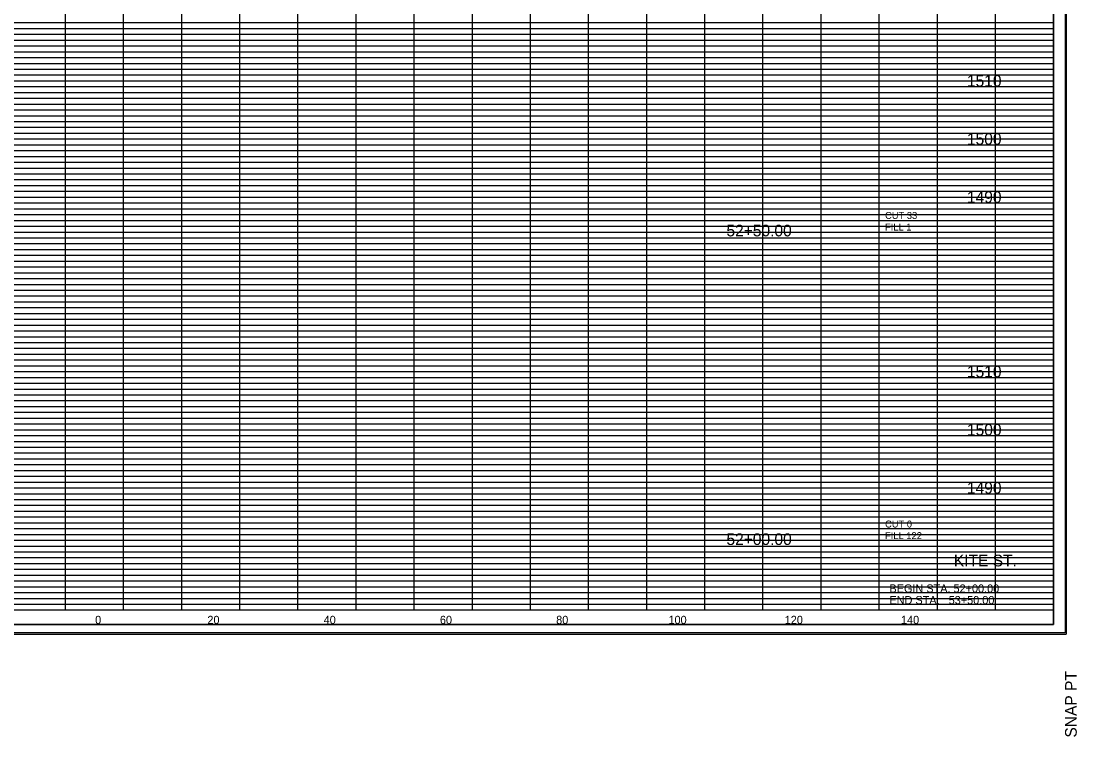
# Model space of a CAD drawing. Extents: x 980 to 1324, y 978 to 1497.
# Drawn here: x 1142.4 to 1324, y 1248.2 to 1371.3 of the extents above; entities that cross this region are included whole.
import ezdxf

# ---------------------------------------------------------------- set-up
doc = ezdxf.new("R2010")
doc.units = 0
for name, color, linetype in [('DESIGN - SHEET - Corner Text', 7, 'Continuous'), ('DESIGN - SHEET - Light Grid', 7, 'Continuous'), ('DESIGN - SHEET - Linework', 7, 'Continuous'), ('DESIGN - SHEET - Plot Shape', 7, 'Continuous'), ('DESIGN - TYPICAL - Text', 7, 'Continuous')]:
    doc.layers.add(name, color=color, linetype=linetype)

# ---------------------------------------------------------------- blocks, each defined once
blk = doc.blocks.new('XSTSHT')
at = {"layer": 'DESIGN - SHEET - Light Grid'}
for p, q in [((8, 10.1), (16, 10.1)), ((16, 10.1), (24, 10.1)), ((24, 10.1), (32, 10.1)), ((8, 9.9), (16, 9.9)), ((16, 9.9), (24, 9.9)), ((24, 9.9), (32, 9.9)), ((8, 9.8), (16, 9.8)), ((8, 9.7), (16, 9.7)), ((16, 9.8), (24, 9.8)), ((16, 9.7), (24, 9.7)), ((24, 9.8), (32, 9.8)), ((24, 9.7), (32, 9.7)), ((8, 9.6), (16, 9.6)), ((8, 9.5), (16, 9.5)), ((16, 9.6), (24, 9.6)), ((16, 9.5), (24, 9.5)), ((24, 9.6), (32, 9.6)), ((24, 9.5), (32, 9.5)), ((8, 9.4), (16, 9.4)), ((8, 9.3), (16, 9.3)), ((16, 9.4), (24, 9.4)), ((16, 9.3), (24, 9.3)), ((24, 9.4), (32, 9.4)), ((24, 9.3), (32, 9.3)), ((8, 9.2), (16, 9.2)), ((8, 9.1), (16, 9.1)), ((16, 9.2), (24, 9.2)), ((16, 9.1), (24, 9.1)), ((24, 9.2), (32, 9.2)), ((24, 9.1), (32, 9.1)), ((8, 8.9), (16, 8.9)), ((16, 8.9), (24, 8.9)), ((24, 8.9), (32, 8.9)), ((8, 8.8), (16, 8.8)), ((16, 8.8), (24, 8.8)), ((24, 8.8), (32, 8.8)), ((8, 8.7), (16, 8.7)), ((8, 8.6), (16, 8.6)), ((16, 8.7), (24, 8.7)), ((16, 8.6), (24, 8.6)), ((24, 8.7), (32, 8.7)), ((24, 8.6), (32, 8.6)), ((8, 8.5), (16, 8.5)), ((8, 8.4), (16, 8.4)), ((16, 8.5), (24, 8.5)), ((16, 8.4), (24, 8.4)), ((24, 8.5), (32, 8.5)), ((24, 8.4), (32, 8.4)), ((8, 8.3), (16, 8.3)), ((8, 8.2), (16, 8.2)), ((16, 8.3), (24, 8.3)), ((16, 8.2), (24, 8.2)), ((24, 8.3), (32, 8.3)), ((24, 8.2), (32, 8.2)), ((8, 8.1), (16, 8.1)), ((16, 8.1), (24, 8.1)), ((24, 8.1), (32, 8.1)), ((8, 7.9), (16, 7.9)), ((16, 7.9), (24, 7.9)), ((24, 7.9), (32, 7.9)), ((8, 7.8), (16, 7.8)), ((8, 7.7), (16, 7.7)), ((16, 7.8), (24, 7.8)), ((16, 7.7), (24, 7.7)), ((24, 7.8), (32, 7.8)), ((24, 7.7), (32, 7.7)), ((8, 7.6), (16, 7.6)), ((8, 7.5), (16, 7.5)), ((16, 7.6), (24, 7.6)), ((16, 7.5), (24, 7.5)), ((24, 7.6), (32, 7.6)), ((24, 7.5), (32, 7.5)), ((8, 7.4), (16, 7.4)), ((8, 7.3), (16, 7.3)), ((16, 7.4), (24, 7.4)), ((16, 7.3), (24, 7.3)), ((24, 7.4), (32, 7.4)), ((24, 7.3), (32, 7.3)), ((8, 7.2), (16, 7.2)), ((8, 7.1), (16, 7.1)), ((16, 7.2), (24, 7.2)), ((16, 7.1), (24, 7.1)), ((24, 7.2), (32, 7.2)), ((24, 7.1), (32, 7.1)), ((8, 6.9), (16, 6.9)), ((8, 6.8), (16, 6.8)), ((16, 6.9), (24, 6.9)), ((16, 6.8), (24, 6.8)), ((24, 6.9), (32, 6.9)), ((24, 6.8), (32, 6.8)), ((8, 6.7), (16, 6.7)), ((8, 6.6), (16, 6.6)), ((16, 6.7), (24, 6.7)), ((16, 6.6), (24, 6.6)), ((24, 6.7), (32, 6.7)), ((24, 6.6), (32, 6.6)), ((8, 6.5), (16, 6.5)), ((8, 6.4), (16, 6.4)), ((16, 6.5), (24, 6.5)), ((16, 6.4), (24, 6.4)), ((24, 6.5), (32, 6.5)), ((24, 6.4), (32, 6.4)), ((8, 6.3), (16, 6.3)), ((8, 6.2), (16, 6.2)), ((16, 6.3), (24, 6.3)), ((16, 6.2), (24, 6.2)), ((24, 6.3), (32, 6.3)), ((24, 6.2), (32, 6.2)), ((8, 6.1), (16, 6.1)), ((16, 6.1), (24, 6.1)), ((24, 6.1), (32, 6.1)), ((8, 5.9), (16, 5.9)), ((16, 5.9), (24, 5.9)), ((24, 5.9), (32, 5.9)), ((8, 5.8), (16, 5.8)), ((8, 5.7), (16, 5.7)), ((16, 5.8), (24, 5.8)), ((16, 5.7), (24, 5.7)), ((24, 5.8), (32, 5.8)), ((24, 5.7), (32, 5.7)), ((8, 5.6), (16, 5.6)), ((8, 5.5), (16, 5.5)), ((16, 5.6), (24, 5.6)), ((16, 5.5), (24, 5.5)), ((24, 5.6), (32, 5.6)), ((24, 5.5), (32, 5.5)), ((8, 5.4), (16, 5.4)), ((8, 5.3), (16, 5.3)), ((16, 5.4), (24, 5.4)), ((16, 5.3), (24, 5.3)), ((24, 5.4), (32, 5.4)), ((24, 5.3), (32, 5.3)), ((8, 5.2), (16, 5.2)), ((8, 5.1), (16, 5.1)), ((16, 5.2), (24, 5.2)), ((16, 5.1), (24, 5.1)), ((24, 5.2), (32, 5.2)), ((24, 5.1), (32, 5.1)), ((8, 4.9), (16, 4.9)), ((8, 4.8), (16, 4.8)), ((16, 4.9), (24, 4.9)), ((16, 4.8), (24, 4.8)), ((24, 4.9), (32, 4.9)), ((24, 4.8), (32, 4.8)), ((8, 4.7), (16, 4.7)), ((8, 4.6), (16, 4.6)), ((16, 4.7), (24, 4.7)), ((16, 4.6), (24, 4.6)), ((24, 4.7), (32, 4.7)), ((24, 4.6), (32, 4.6)), ((8, 4.5), (16, 4.5)), ((8, 4.4), (16, 4.4)), ((16, 4.5), (24, 4.5)), ((16, 4.4), (24, 4.4)), ((24, 4.5), (32, 4.5)), ((24, 4.4), (32, 4.4)), ((8, 4.3), (16, 4.3)), ((8, 4.2), (16, 4.2)), ((16, 4.3), (24, 4.3)), ((16, 4.2), (24, 4.2)), ((24, 4.3), (32, 4.3)), ((24, 4.2), (32, 4.2)), ((8, 4.1), (16, 4.1)), ((16, 4.1), (24, 4.1)), ((24, 4.1), (32, 4.1)), ((8, 3.9), (16, 3.9)), ((16, 3.9), (24, 3.9)), ((24, 3.9), (32, 3.9)), ((8, 3.8), (16, 3.8)), ((8, 3.7), (16, 3.7)), ((16, 3.8), (24, 3.8)), ((16, 3.7), (24, 3.7)), ((24, 3.8), (32, 3.8)), ((24, 3.7), (32, 3.7)), ((8, 3.6), (16, 3.6)), ((8, 3.5), (16, 3.5)), ((16, 3.6), (24, 3.6)), ((16, 3.5), (24, 3.5)), ((24, 3.6), (32, 3.6)), ((24, 3.5), (32, 3.5)), ((8, 3.4), (16, 3.4)), ((8, 3.3), (16, 3.3)), ((16, 3.4), (24, 3.4)), ((16, 3.3), (24, 3.3)), ((24, 3.4), (32, 3.4)), ((24, 3.3), (32, 3.3)), ((8, 3.2), (16, 3.2)), ((8, 3.1), (16, 3.1)), ((16, 3.2), (24, 3.2)), ((16, 3.1), (24, 3.1)), ((24, 3.2), (32, 3.2)), ((24, 3.1), (32, 3.1)), ((8, 2.9), (16, 2.9)), ((8, 2.8), (16, 2.8)), ((16, 2.9), (24, 2.9)), ((16, 2.8), (24, 2.8)), ((24, 2.9), (32, 2.9)), ((24, 2.8), (32, 2.8)), ((8, 2.7), (16, 2.7)), ((8, 2.6), (16, 2.6)), ((16, 2.7), (24, 2.7)), ((16, 2.6), (24, 2.6)), ((24, 2.7), (32, 2.7)), ((24, 2.6), (32, 2.6)), ((8, 2.5), (16, 2.5)), ((8, 2.4), (16, 2.4)), ((16, 2.5), (24, 2.5)), ((16, 2.4), (24, 2.4)), ((24, 2.5), (32, 2.5)), ((24, 2.4), (32, 2.4)), ((8, 2.3), (16, 2.3)), ((8, 2.2), (16, 2.2)), ((16, 2.3), (24, 2.3)), ((16, 2.2), (24, 2.2)), ((24, 2.3), (32, 2.3)), ((24, 2.2), (32, 2.2)), ((8, 2.1), (16, 2.1)), ((16, 2.1), (24, 2.1)), ((24, 2.1), (32, 2.1)), ((8, 1.9), (16, 1.9)), ((16, 1.9), (24, 1.9)), ((24, 1.9), (32, 1.9)), ((8, 1.8), (16, 1.8)), ((8, 1.7), (16, 1.7)), ((16, 1.8), (24, 1.8)), ((16, 1.7), (24, 1.7)), ((24, 1.8), (32, 1.8)), ((24, 1.7), (32, 1.7)), ((8, 1.6), (16, 1.6)), ((8, 1.5), (16, 1.5)), ((16, 1.6), (24, 1.6)), ((16, 1.5), (24, 1.5)), ((24, 1.6), (32, 1.6)), ((24, 1.5), (32, 1.5)), ((8, 1.4), (16, 1.4)), ((8, 1.3), (16, 1.3)), ((16, 1.4), (24, 1.4)), ((16, 1.3), (24, 1.3)), ((24, 1.4), (32, 1.4)), ((24, 1.3), (32, 1.3)), ((8, 1.2), (16, 1.2)), ((8, 1.1), (16, 1.1)), ((16, 1.2), (24, 1.2)), ((16, 1.1), (24, 1.1)), ((24, 1.2), (32, 1.2)), ((24, 1.1), (32, 1.1)), ((8, 0.9), (16, 0.9)), ((8, 0.8), (16, 0.8)), ((16, 0.9), (24, 0.9)), ((16, 0.8), (24, 0.8)), ((24, 0.9), (32, 0.9)), ((24, 0.8), (32, 0.8)), ((8, 0.7), (16, 0.7)), ((8, 0.6), (16, 0.6)), ((16, 0.7), (24, 0.7)), ((16, 0.6), (24, 0.6)), ((24, 0.7), (32, 0.7)), ((24, 0.6), (32, 0.6)), ((8, 0.5), (16, 0.5)), ((8, 0.4), (16, 0.4)), ((16, 0.5), (24, 0.5)), ((16, 0.4), (24, 0.4)), ((24, 0.5), (32, 0.5)), ((24, 0.4), (32, 0.4)), ((8, 0.3), (16, 0.3)), ((8, 0.2), (16, 0.2)), ((16, 0.3), (24, 0.3)), ((16, 0.2), (24, 0.2)), ((24, 0.3), (32, 0.3)), ((24, 0.2), (32, 0.2)), ((8, 0.1), (16, 0.1)), ((16, 0.1), (24, 0.1)), ((24, 0.1), (32, 0.1))]:
    blk.add_line(p, q, dxfattribs=at)
at = {"layer": 'DESIGN - SHEET - Linework'}
for p, q in [((32.217, 21.414), (32.217, -0.414)), ((15, 0), (15, 21)), ((16, 0), (16, 21)), ((17, 0), (17, 21)), ((18, 0), (18, 21)), ((19, 0), (19, 21)), ((20, 0), (20, 21)), ((21, 0), (21, 21)), ((22, 0), (22, 21)), ((23, 0), (23, 21)), ((24, 0), (24, 21)), ((25, 0), (25, 21)), ((26, 0), (26, 21)), ((27, 0), (27, 21)), ((28, 0), (28, 20)), ((29, 0), (29, 20)), ((30, 0), (30, 20)), ((31, 0), (31, 20)), ((0, 10), (32, 10)), ((0, 9), (32, 9)), ((0, 8), (32, 8)), ((0, 7), (32, 7)), ((0, 6), (32, 6)), ((0, 5), (32, 5)), ((0, 4), (32, 4)), ((0, 3), (32, 3)), ((0, 2), (32, 2)), ((0, 1), (32, 1)), ((-1.823, -0.414), (32.217, -0.414))]:
    blk.add_line(p, q, dxfattribs=at)
blk.add_lwpolyline([(0, 21), (0, 0), (32, 0), (32, 21), (0, 21)], dxfattribs=at)
at = {"layer": 'DESIGN - SHEET - Plot Shape'}
for points in [[(-1.803, 21.394), (32.197, 21.394), (32.197, -0.394), (-1.803, -0.394)], [(-0.85, 21), (32, 21), (32, -0.25), (-0.85, -0.25)]]:
    blk.add_lwpolyline(points, close=True, dxfattribs=at)
at = {"layer": 'DESIGN - SHEET - Corner Text'}
blk.add_text('SNAP PT  ', height=0.2, rotation=90, dxfattribs=at).set_placement((32.397, -2.194))

msp = doc.modelspace()

# ---------------------------------------------------------------- linework, layer by layer
at = {"layer": 'DESIGN - SHEET - Plot Shape'}
msp.add_lwpolyline([(991.5, 1267.5), (1320, 1267.5), (1320, 1480), (991.5, 1480)], close=True, dxfattribs=at)

# ---------------------------------------------------------------- block references
at = {"layer": 'DESIGN - TYPICAL - Text', "xscale": 10, "yscale": 10}
msp.add_blockref('XSTSHT', (1000, 1270), dxfattribs=at)

# ---------------------------------------------------------------- texts
at = {"layer": 'DESIGN - SHEET - Corner Text'}
for s, height, p in [('KITE ST.', 2, (1302.83, 1277.5)), ('BEGIN STA. 52+00.00', 1.4, (1291.75, 1273)), ('END STA.   53+50.00', 1.4, (1291.75, 1271))]:
    msp.add_text(s, height=height, dxfattribs=at).set_placement(p)
at = {"layer": 'DESIGN - TYPICAL - Text'}
for s, height, p in [('     1510     ', 2, (1301.37, 1360)), ('     1500     ', 2, (1301.37, 1350)), ('     1490     ', 2, (1301.37, 1340)), ('CUT 33', 1.2, (1291, 1337.25)), ('     52+50.00     ', 2, (1260, 1334.25)), ('FILL 1', 1.2, (1291, 1335.25)), ('     1510     ', 2, (1301.37, 1310)), ('     1500     ', 2, (1301.37, 1300)), ('     1490     ', 2, (1301.37, 1290)), ('CUT 0', 1.2, (1291, 1284.18)), ('     52+00.00     ', 2, (1260, 1281.18)), ('FILL 122', 1.2, (1291, 1282.18)), ('     0     ', 1.4, (1152.51, 1267.6)), ('     0     ', 1.4, (1152.51, 1267.6)), ('     20     ', 1.4, (1171.82, 1267.6)), ('     40     ', 1.4, (1191.82, 1267.6)), ('     60     ', 1.4, (1211.82, 1267.6)), ('     80     ', 1.4, (1231.82, 1267.6)), ('     100     ', 1.4, (1251.14, 1267.6)), ('     120     ', 1.4, (1271.14, 1267.6)), ('     140     ', 1.4, (1291.14, 1267.6))]:
    msp.add_text(s, height=height, dxfattribs=at).set_placement(p)

doc.saveas('drawing.dxf')
